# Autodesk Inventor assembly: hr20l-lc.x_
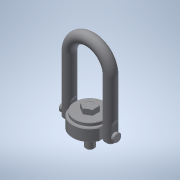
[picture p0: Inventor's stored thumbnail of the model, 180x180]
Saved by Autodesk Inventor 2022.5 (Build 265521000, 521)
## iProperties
Part Number: hr20l-lc.x_
Material: 一般
Document SubType Name: Assembly
Designer: ImaoCorp
Sending System: SOLIDWORKS 2017-2017317
MC: AMD64
MC_MODEL: Intel64 Family 6 Model 60 Stepping 3, GenuineIntel
OS: Windows_NT
FRU: Parasolid Version 29.0, build 201,  4-17-2017
FORMAT: text
GUISE: transmit
KEY: hr20l-lc
FILE: hr20l-lc.x_t
DATE: Mon Jul 01 17:37:48 2019
Author: ImaoCorp
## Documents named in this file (3)
- X:\14_SW2022-Inv2022\00_全2023-1023新製品(TCC)まで\h\hr20l-lc\HR20L-LC.iam
- X:\14_SW2022-Inv2022\00_全2023-1023新製品(TCC)まで\h\hr20l-lc\hr20l-lc_01.ipt
- X:\14_SW2022-Inv2022\00_全2023-1023新製品(TCC)まで\h\hr20l-lc\hr20l-lc_02.ipt
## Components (2 placed, 2 different names)
1. hr20l-lc_01
2. hr20l-lc_02
